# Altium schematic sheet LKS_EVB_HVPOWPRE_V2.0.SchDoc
size A3; SheetNumber: 0; SheetTotal: 0
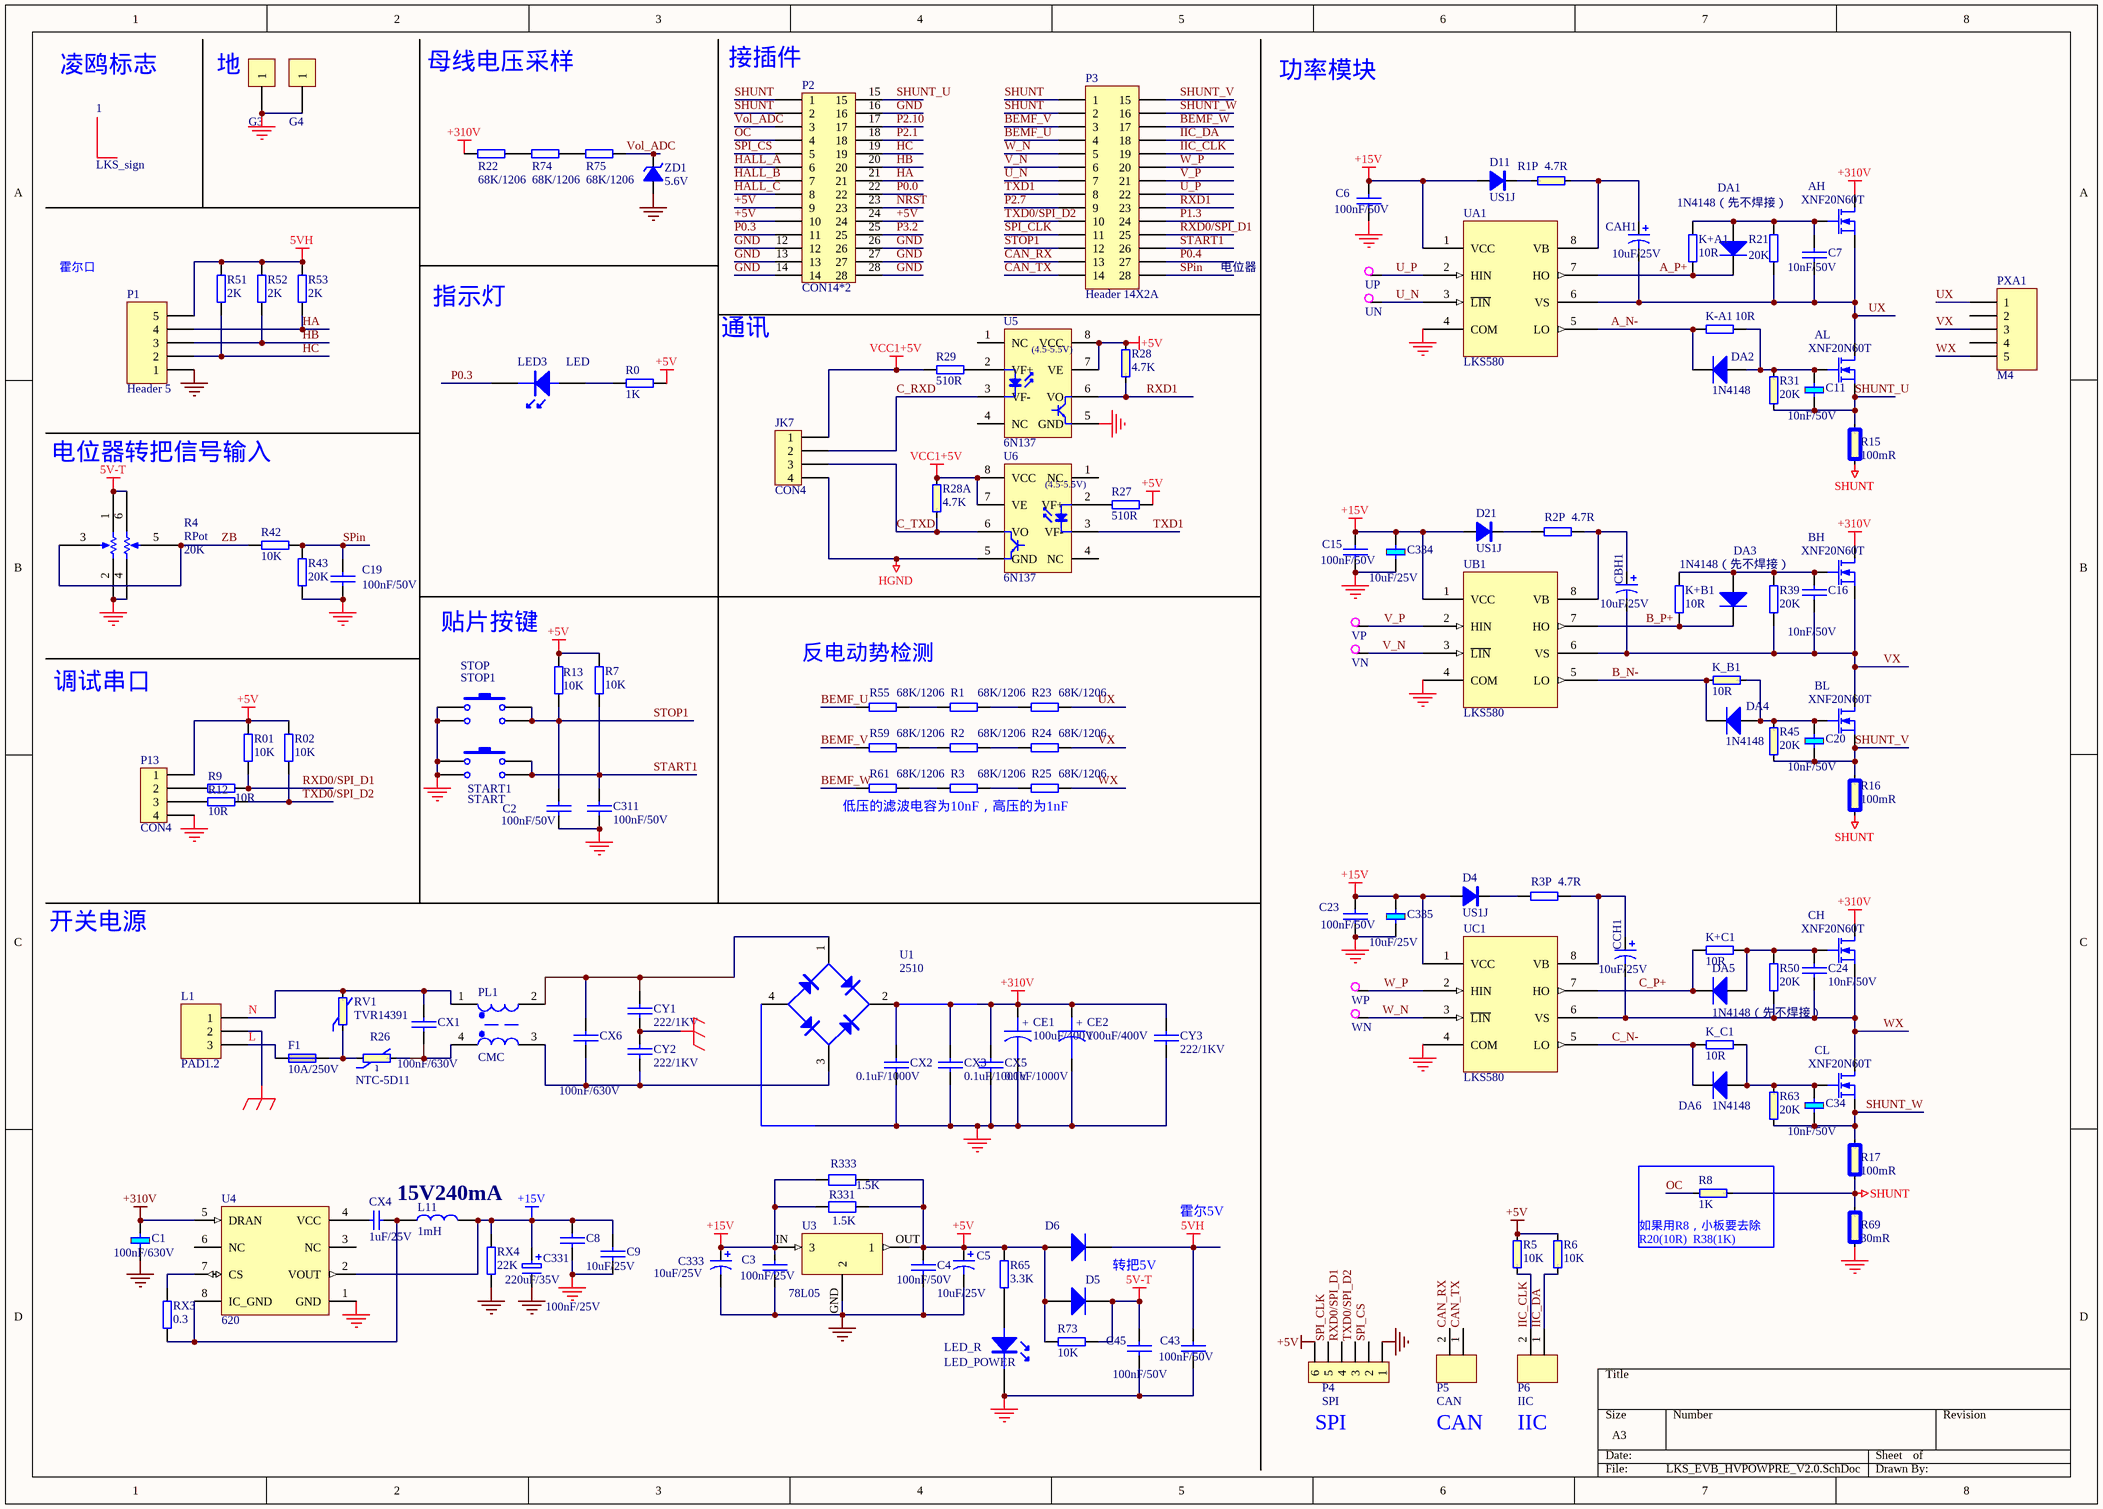
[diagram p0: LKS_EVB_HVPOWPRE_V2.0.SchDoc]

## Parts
1  LKS_sign  [PCBComponent_1]
AH  XNF20N60T  [TO-220散热片]
AL  XNF20N60T  [TO-220散热片]
BH  XNF20N60T  [TO-220散热片]
BL  XNF20N60T  [TO-220散热片]
C1  100nF/630V
C2  100nF/50V  [0805C]
C3  100nF/25V  [0805C]
C4  100nF/50V  [0603C]
C5  10uF/25V  [0603C]
C6  100nF/50V  [0805C]
C7  10nF/50V  [0805C]
C8  100nF/25V  [0805C]
C9  10uF/25V  [0603C]
C11  10nF/50V
C15  100nF/50V  [0805C]
C16  10nF/50V  [0805C]
C19  100nF/50V  [0805C]
C20  10nF/50V
C23  100nF/50V  [0805C]
C24  10nF/50V  [0805C]
C34  10nF/50V
C43  100nF/50V  [0805C]
C45  100nF/50V  [0805C]
C311  100nF/50V  [0805C]
C331  220uF/35V  [EC-8.0-1]
C333  10uF/25V  [1206]
C334  10uF/25V
C335  10uF/25V
CAH1  10uF/25V  [1206]
CBH1  10uF/25V  [1206]
CCH1  10uF/25V  [1206]
CE1  100uF/400V  [CE-7.5*16]
CE2  100uF/400V  [CE-7.5*16]
CH  XNF20N60T  [TO-220散热片]
CL  XNF20N60T  [TO-220散热片]
CX1  100nF/630V  [C-X]
CX2  0.1uF/1000V  [1812(4532) - POLARIZED]
CX3  0.1uF/1000V  [1812(4532) - POLARIZED]
CX4  1uF/25V  [0805C]
CX5  0.1uF/1000V  [1812(4532) - POLARIZED]
CX6  100nF/630V  [C-X]
CY1  222/1KV  [C-Y]
CY2  222/1KV  [C-Y]
CY3  222/1KV  [C-Y]
D4  US1J
D5  1N4007  [D1206]  (value not drawn)
D6  1N4007  [D1206]  (value not drawn)
D11  US1J
D21  US1J
DA1  1N4148（先不焊接）  [D1206]
DA2  1N4148  [D1206]
DA3  1N4148（先不焊接）  [D1206]
DA4  1N4148  [D1206]
DA5  1N4148（先不焊接）  [D1206]
DA6  1N4148  [D1206]
F1  10A/250V
G3  PAD1.2  [PAD1.2]  (value not drawn)
G4  PAD1.2  [PAD1.2]  (value not drawn)
JK7  CON4
K+A1  10R  [0805R]
K+B1  10R  [0805R]
K+C1  10R  [0805R]
K-A1  10R  [0805R]
K_B1  10R
K_C1  10R  [0805R]
L1  PAD1.2  [栅栏式7.62间距3P]
L11  1mH  [L-8*10]
LED3  LED  [0805D]
LED_POWER  LED_R  [0805D]
P1  Header 5  [2.54-XH-5A-180]
P2  CON14*2
P3  Header 14X2A  [HDR2X14_CEN]
P4  SPI
P5  CAN
P6  IIC
P13  CON4
PL1  CMC  [立式电感（背面）]
PXA1  M4  [栅栏式7.62间距5P]
R0  1K  [0805R]
R1  68K/1206  [1206]
R01  10K  [0805R]
R1P  4.7R
R2  68K/1206  [1206]
R02  10K  [0805R]
R2P  4.7R  [1206]
R3  68K/1206  [1206]
R3P  4.7R  [1206]
R4  RPot  value 20K  [RK097-W]
R5  10K
R6  10K
R7  10K  [0805R]
R8  1K
R9  10R  [0805R]
R12  10R  [0805R]
R13  10K  [0805R]
R15  100mR
R16  100mR
R17  100mR
R21  20K  [0805R]
R22  68K/1206  [1206]
R23  68K/1206  [1206]
R24  68K/1206  [1206]
R25  68K/1206  [1206]
R26  NTC-5D11
R27  510R  [0805R]
R28  4.7K
R28A  4.7K
R29  510R  [0805]
R31  20K
R39  20K  [0805R]
R42  10K  [0805R]
R43  20K  [0805R]
R45  20K
R50  20K  [0805R]
R51  2K  [0805R]
R52  2K  [0805R]
R53  2K  [0805R]
R55  68K/1206  [1206]
R59  68K/1206  [1206]
R61  68K/1206  [1206]
R63  20K
R65  3.3K  [0805R]
R69  30mR
R73  10K  [0805R]
R74  68K/1206  [1206]
R75  68K/1206  [1206]
R331  value 1.5K  [0805R]  (hidden comment: 0603)
R333  value 1.5K  [0805R]  (hidden comment: 0603)
RV1  TVR14391
RX3  0.3  [0805R]
RX4  22K  [0805R]
START1  START  [SW-PB  12*12]
STOP1  STOP  [SW-PB  12*12]
U1  2510  [_Bridge1]
U3  78L05
U4  620
U5  6N137
U6  6N137
UA1  LKS580  [SO-8]
UB1  LKS580  [SO-8]
UC1  LKS580  [SO-8]
UN  TestP  [TP-40]  (value not drawn)
UP  TestP  [TP-40]  (value not drawn)
VN  TestP  [TP-40]  (value not drawn)
VP  TestP  [TP-40]  (value not drawn)
WN  TestP  [TP-40]  (value not drawn)
WP  TestP  [TP-40]  (value not drawn)
ZD1  5.6V

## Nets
5V-T: C45.2 D5.2(K) R4.1(TOP) R4.6(TOP) R73.2
5VH: C43.2 D6.2(K) P1.5 R51.2 R52.2 R53.2
+5V: C4.2 C5.1 D5.1(A) D6.1(A) P2.9 P2.10 P2.24 P4.6 P13.1 R0.2 R01.2 R02.2 R5.2 R6.2 R7.1 R13.1 R27.2 R28.2 R65.1 R73.1 R331.2 R333.2 U3.OUT(1) U5.7(VE) U5.8(VCC)
+15V: C3.2 C6.2 C8.1 C9.2 C15.2 C23.2 C331.1 C333.1 C334.1 C335.1 D4.A D11.A D21.A L11.2 R331.1 R333.1 RX4.2 U3.IN(3) U4.2(VOUT) UA1.1(VCC) UB1.1(VCC) UC1.1(VCC)
+310V: AH.2(D) BH.2(D) C1.1 CE1.1 CE2.1 CH.2(D) CX2.1 CX3.1 CX5.1 CY3.1 R22.1 U1.2(V+) U4.5(DRAN)
GND: C1.2 C2.1 C3.1 C4.1 C5.2 C6.1 C8.2 C9.1 C15.1 C19.1 C23.1 C43.1 C45.1 C311.1 C331.2 C333.2 C334.2 C335.2 CE1.2 CE2.2 CX2.2 CX3.2 CX5.2 CY3.2 G3.1 G4.1 LED_POWER.2(K) P1.1 P2.12 P2.13 P2.14 P2.16 P2.26 P2.27 P2.28 P4.1 P13.4 R4.2(TAP) R4.4(BOT) R43.1 R69.2 RX4.1 START1.1 START1.3 STOP1.1 STOP1.3 U1.4(V-) U3.GND(2) U4.1(GND) U5.5(GND) UA1.4(COM) UB1.4(COM) UC1.4(COM) ZD1.A
HGND: JK7.4 U6.5(GND)
PE: CY1.1 CY2.2 L1.2
SHUNT: P2.1 P2.2 P3.1 P3.2 R8.1 R15.2 R16.2 R17.2 R69.1
VCC1+5V: JK7.1 R28A.2 R29.1 U6.7(VE) U6.8(VCC)
A_N-: DA2.2(K) K-A1.2 UA1.5(LO)
A_P+: DA1.2(K) K+A1.1 UA1.7(HO)
B_N-: DA4.2(K) K_B1.2 UB1.5(LO)
B_P+: DA3.2(K) K+B1.1 UB1.7(HO)
BEMF_U: P3.4 R55.1
BEMF_V: P3.3 R59.1
BEMF_W: P3.17 R61.1
C_N-: DA6.2(K) K_C1.2 UC1.5(LO)
C_P+: DA5.2(K) K+C1.1 UC1.7(HO)
C_RXD: JK7.2 U5.3(VF-)
C_TXD: JK7.3 R28A.1 U6.6(VO)
CAN_RX: P3.13 P5.2
CAN_TX: P3.14 P5.1
HA: P1.4 P2.21 R53.1
HALL_A: P2.6
HALL_B: P2.7
HALL_C: P2.8
HB: P1.3 P2.20 R52.1
HC: P1.2 P2.19 R51.1
IIC_CLK: P3.19 P6.2 R5.1
IIC_DA: P3.18 P6.1 R6.1
L: F1.1 L1.3
N: CX1.1 L1.1 PL1.1 RV1.1
NRST: P2.23
OC: P2.4 R8.2
P0.0: P2.22
P0.3: LED3.2(K) P2.11
P0.4: P3.27
P1.3: P3.24
P2.1: P2.18
P2.7: P3.9
P2.10: P2.17
P3.2: P2.25
RXD0/SPI_D1: P3.25 P4.4 R01.1 R9.1
RXD1: P3.23 R28.1 U5.6(VO)
SHUNT_U: AL.3(S) C11.2 P2.15 R15.1 R31.2
SHUNT_V: BL.3(S) C20.2 P3.15 R16.1 R45.2
SHUNT_W: C34.2 CL.3(S) P3.16 R17.1 R63.2
SPI_CLK: P3.11 P4.5
SPI_CS: P2.5 P4.2
SPin: C19.2 P3.28 R42.2 R43.2
START1: C311.2 P3.26 R7.2 START1.2 START1.4
STOP1: C2.2 P3.12 R13.2 STOP1.2 STOP1.4
TXD0/SPI_D2: P3.10 P4.3 R02.1 R12.1
TXD1: P3.8 U6.3(VF-)
U_N: P3.7 UA1.3(~{LIN}) UN.1
U_P: P3.22 UA1.2(HIN) UP.1
UX: AH.3(S) AL.2(D) C7.2 CAH1.2 PXA1.1 R21.1 R23.2 UA1.6(VS)
V_N: P3.6 UB1.3(~{LIN}) VN.1
V_P: P3.21 UB1.2(HIN) VP.1
Vol_ADC: P2.3 R75.2 ZD1.K
VX: BH.3(S) BL.2(D) C16.2 CBH1.2 PXA1.3 R24.2 R39.1 UB1.6(VS)
W_N: P3.5 UC1.3(~{LIN}) WN.1
W_P: P3.20 UC1.2(HIN) WP.1
WX: C24.2 CCH1.2 CH.3(S) CL.2(D) PXA1.5 R25.2 R50.1 UC1.6(VS)
ZB: R4.3(BOT) R4.5(TAP) R42.1
NetAH_1: AH.1(G) C7.1 DA1.1(A) K+A1.2 R21.2
NetAL_1: AL.1(G) C11.1 DA2.1(A) K-A1.1 R31.1
NetBH_1: BH.1(G) C16.1 DA3.1(A) K+B1.2 R39.2
NetBL_1: BL.1(G) C20.1 DA4.1(A) K_B1.1 R45.1
NetC24_1: C24.1 CH.1(G) DA5.1(A) K+C1.2 R50.2
NetC34_1: C34.1 CL.1(G) DA6.1(A) K_C1.1 R63.1
NetCAH1_1: CAH1.1 R1P.2 UA1.8(VB)
NetCBH1_1: CBH1.1 R2P.2 UB1.8(VB)
NetCCH1_1: CCH1.1 R3P.2 UC1.8(VB)
NetCX1_2: CX1.2 PL1.4 R26.1
NetCX4_1: CX4.1 U4.4(VCC)
NetCX4_2: CX4.2 L11.1 RX3.2 U4.8(IC_GND)
NetCX6_1: CX6.1 CY1.2 PL1.2 U1.1(AC)
NetCX6_2: CX6.2 CY2.1 PL1.3 U1.3(AC)
NetD4_K: D4.K R3P.1
NetD11_K: D11.K R1P.1
NetD21_K: D21.K R2P.1
NetF1_2: F1.2 R26.2 RV1.2
NetLED3_1: LED3.1(A) R0.1
NetLED_POWER_1: LED_POWER.1(A) R65.2
NetP13_2: P13.2 R9.2
NetP13_3: P13.3 R12.2
NetR1_1: R1.1 R55.2
NetR1_2: R1.2 R23.1
NetR2_1: R2.1 R59.2
NetR2_2: R2.2 R24.1
NetR3_1: R3.1 R61.2
NetR3_2: R3.2 R25.1
NetR22_2: R22.2 R74.1
NetR27_1: R27.1 U6.2(VF+)
NetR29_2: R29.2 U5.2(VF+)
NetR74_2: R74.2 R75.1
NetRX3_1: RX3.1 U4.7(CS)

Not connected (* = marked no-connect by the designer): PXA1 2 4; U4 3(NC) 6(NC); U5 1(NC) 4(NC); U6 1(NC) 4(NC)

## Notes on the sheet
- (near 1) 凌鸥标志
- (near G3) 地
- 母线电压采样
- (near P2) 接插件
- 功率模块
- 霍尔口
- 指示灯
- 电位器
- 通讯
- 转把信号输入
- 贴片按键
- 调试串口
- (near R55) 反电动势检测
- 低压的滤波电容为10nF，高压的为1nF
- 开关电源
- 15V240mA
- 霍尔5V
- (near R8) R20(10R)
- (near R8) 如果用R8，小板要去除
- (near R8) R38(1K)
- 转把5V
- (near P4) SPI
- CAN
- IIC

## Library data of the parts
AH AL BH BL CH CL = MOS
C1 C11 C20 C34 C334 C335 = CAP
C2-C4 C6-C9 C15 C16 C19 C23 C24 C43 C45 C311 = C: Capacitor
C5 C333 CAH1 CBH1 CCH1 = Cap Pol1: Polarized Capacitor (Radial); Value: 47uF/50V
C331 = EC
CE1 CE2 = CAPACITOR POL: Capacitor
CX1-CX3 CX5 CX6 CY3 = CAP: Capacitor_10nJ/630V
CX4 = CAP-1
CY1 CY2 = CAP: Capacitor_103/1KV
D4 D11 D21 = DIODE
D5 D6 = Diode 1N4007: 1 Amp General Purpose Rectifier
DA1-DA6 = Diode: Default Diode
F1 = FUSE
G3 G4 = CON1: Connector
K+A1 K+B1 K+C1 K-A1 K_C1 R0 R1 R01 R2 R02 R2P R3 R3P R7 R9 R12 R13 R21-R25 R27 R39 R42 R43 R50-R53 R55 R59 R61 R65 R73-R75 = RES/1
K_B1 R1P R5 R6 R8 R28 R28A R31 R45 R63 = RES2
L1 = Header 3: Header, 3-Pin
L11 = INDUCTOR1
LED_POWER = LED
P1 PXA1 = Header 5: Header, 5-Pin
P3 = Header 14X2A: Header, 14-Pin, Dual row
P4 = CON6
P5 P6 = CON2
PL1 = COMML
R4 = RPot: Potentiometer; Sim Note: Enter the Resistance value and the set point into parameter fields.; Set Position: 0.5
R15-R17 R69 = RES2L
R26 = R-NTC
R29 = RES2短
R331 R333 = Res2: Resistor
RV1 = RV
RX3 RX4 = RES2-1
START1 STOP1 = SW-PB: Switch
U1 = BRIDGE1: Diode Bridge
UA1 UB1 UC1 = LKS560/LKS580
ZD1 = ZW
